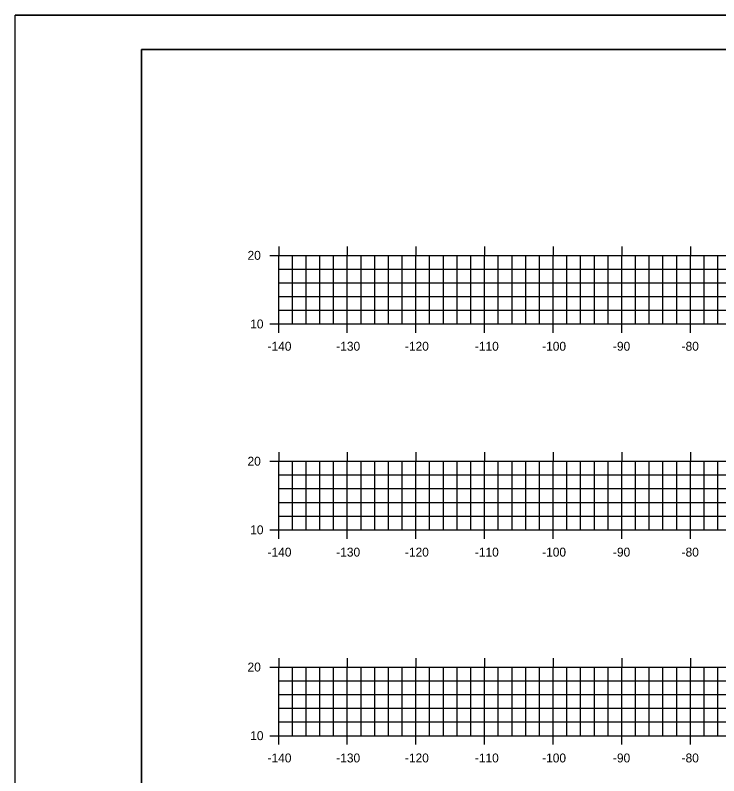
# Model space of a CAD drawing. Extents: x 40011 to 50684, y 49949 to 72236.
# Drawn here: x 41164.2 to 41266.7, y 69083.8 to 69194.6 of the extents above; entities that cross this region are included whole.
import ezdxf

# ---------------------------------------------------------------- set-up
doc = ezdxf.new("R2010")
doc.units = 0
for name, color, linetype in [('1', 7, 'Continuous'), ('41', 7, 'Continuous'), ('51', 7, 'Continuous'), ('53', 7, 'Continuous'), ('55', 7, 'Continuous'), ('60', 7, 'Continuous')]:
    doc.layers.add(name, color=color, linetype=linetype)

msp = doc.modelspace()

# ---------------------------------------------------------------- linework, layer by layer
at = {"layer": '1'}
for p, q in [((41513.59, 69194.6), (41164.2, 69194.6)), ((41182.59, 69189.6), (41182.59, 68979.6)), ((41512.59, 69189.6), (41182.59, 69189.6))]:
    msp.add_line(p, q, dxfattribs=at)
at = {"layer": '41'}
for points in [[(41164.2, 69194.6), (41513.59, 69194.6), (41513.59, 68974.6), (41164.2, 68974.6)], [(41182.59, 69189.6), (41512.59, 69189.6), (41512.59, 68979.6), (41182.59, 68979.6)]]:
    msp.add_lwpolyline(points, close=True, dxfattribs=at)
at = {"layer": '51'}
for p, q in [((41201.29, 69159.6), (41202.59, 69159.6)), ((41202.59, 69149.6), (41202.59, 69159.6)), ((41204.59, 69149.6), (41204.59, 69159.6)), ((41206.59, 69149.6), (41206.59, 69159.6)), ((41208.59, 69149.6), (41208.59, 69159.6)), ((41210.59, 69149.6), (41210.59, 69159.6)), ((41214.59, 69149.6), (41214.59, 69159.6)), ((41216.59, 69149.6), (41216.59, 69159.6)), ((41218.59, 69149.6), (41218.59, 69159.6)), ((41220.59, 69149.6), (41220.59, 69159.6)), ((41224.59, 69149.6), (41224.59, 69159.6)), ((41226.59, 69149.6), (41226.59, 69159.6)), ((41228.59, 69149.6), (41228.59, 69159.6)), ((41230.59, 69149.6), (41230.59, 69159.6)), ((41234.59, 69149.6), (41234.59, 69159.6)), ((41236.59, 69149.6), (41236.59, 69159.6)), ((41238.59, 69149.6), (41238.59, 69159.6)), ((41240.59, 69149.6), (41240.59, 69159.6)), ((41244.59, 69149.6), (41244.59, 69159.6)), ((41246.59, 69149.6), (41246.59, 69159.6)), ((41248.59, 69149.6), (41248.59, 69159.6)), ((41250.59, 69149.6), (41250.59, 69159.6)), ((41254.59, 69149.6), (41254.59, 69159.6)), ((41256.59, 69149.6), (41256.59, 69159.6)), ((41258.59, 69149.6), (41258.59, 69159.6)), ((41260.59, 69149.6), (41260.59, 69159.6)), ((41264.59, 69149.6), (41264.59, 69159.6)), ((41266.59, 69149.6), (41266.59, 69159.6)), ((41201.29, 69149.6), (41202.59, 69149.6)), ((41202.59, 69149.6), (41482.59, 69149.6)), ((41202.59, 69148.3), (41202.59, 69149.6)), ((41212.59, 69148.3), (41212.59, 69149.6)), ((41222.59, 69148.3), (41222.59, 69149.6)), ((41232.59, 69148.3), (41232.59, 69149.6)), ((41242.59, 69148.3), (41242.59, 69149.6)), ((41252.59, 69148.3), (41252.59, 69149.6)), ((41262.59, 69148.3), (41262.59, 69149.6)), ((41201.29, 69129.6), (41202.59, 69129.6)), ((41202.59, 69119.6), (41202.59, 69129.6)), ((41204.59, 69119.6), (41204.59, 69129.6)), ((41206.59, 69119.6), (41206.59, 69129.6)), ((41208.59, 69119.6), (41208.59, 69129.6)), ((41210.59, 69119.6), (41210.59, 69129.6)), ((41214.59, 69119.6), (41214.59, 69129.6)), ((41216.59, 69119.6), (41216.59, 69129.6)), ((41218.59, 69119.6), (41218.59, 69129.6)), ((41220.59, 69119.6), (41220.59, 69129.6)), ((41224.59, 69119.6), (41224.59, 69129.6)), ((41226.59, 69119.6), (41226.59, 69129.6)), ((41228.59, 69119.6), (41228.59, 69129.6)), ((41230.59, 69119.6), (41230.59, 69129.6)), ((41234.59, 69119.6), (41234.59, 69129.6)), ((41236.59, 69119.6), (41236.59, 69129.6)), ((41238.59, 69119.6), (41238.59, 69129.6)), ((41240.59, 69119.6), (41240.59, 69129.6)), ((41244.59, 69119.6), (41244.59, 69129.6)), ((41246.59, 69119.6), (41246.59, 69129.6)), ((41248.59, 69119.6), (41248.59, 69129.6)), ((41250.59, 69119.6), (41250.59, 69129.6)), ((41254.59, 69119.6), (41254.59, 69129.6)), ((41256.59, 69119.6), (41256.59, 69129.6)), ((41258.59, 69119.6), (41258.59, 69129.6)), ((41260.59, 69119.6), (41260.59, 69129.6)), ((41264.59, 69119.6), (41264.59, 69129.6)), ((41266.59, 69119.6), (41266.59, 69129.6)), ((41201.29, 69119.6), (41202.59, 69119.6)), ((41202.59, 69119.6), (41482.59, 69119.6)), ((41202.59, 69118.3), (41202.59, 69119.6)), ((41212.59, 69118.3), (41212.59, 69119.6)), ((41222.59, 69118.3), (41222.59, 69119.6)), ((41232.59, 69118.3), (41232.59, 69119.6)), ((41242.59, 69118.3), (41242.59, 69119.6)), ((41252.59, 69118.3), (41252.59, 69119.6)), ((41262.59, 69118.3), (41262.59, 69119.6)), ((41201.29, 69099.6), (41202.59, 69099.6)), ((41202.59, 69089.6), (41202.59, 69099.6)), ((41204.59, 69089.6), (41204.59, 69099.6)), ((41206.59, 69089.6), (41206.59, 69099.6)), ((41208.59, 69089.6), (41208.59, 69099.6)), ((41210.59, 69089.6), (41210.59, 69099.6)), ((41214.59, 69089.6), (41214.59, 69099.6)), ((41216.59, 69089.6), (41216.59, 69099.6)), ((41218.59, 69089.6), (41218.59, 69099.6)), ((41220.59, 69089.6), (41220.59, 69099.6)), ((41224.59, 69089.6), (41224.59, 69099.6)), ((41226.59, 69089.6), (41226.59, 69099.6)), ((41228.59, 69089.6), (41228.59, 69099.6)), ((41230.59, 69089.6), (41230.59, 69099.6)), ((41234.59, 69089.6), (41234.59, 69099.6)), ((41236.59, 69089.6), (41236.59, 69099.6)), ((41238.59, 69089.6), (41238.59, 69099.6)), ((41240.59, 69089.6), (41240.59, 69099.6)), ((41244.59, 69089.6), (41244.59, 69099.6)), ((41246.59, 69089.6), (41246.59, 69099.6)), ((41248.59, 69089.6), (41248.59, 69099.6)), ((41250.59, 69089.6), (41250.59, 69099.6)), ((41254.59, 69089.6), (41254.59, 69099.6)), ((41256.59, 69089.6), (41256.59, 69099.6)), ((41258.59, 69089.6), (41258.59, 69099.6)), ((41260.59, 69089.6), (41260.59, 69099.6)), ((41264.59, 69089.6), (41264.59, 69099.6)), ((41266.59, 69089.6), (41266.59, 69099.6)), ((41201.29, 69089.6), (41202.59, 69089.6)), ((41202.59, 69089.6), (41482.59, 69089.6)), ((41202.59, 69088.3), (41202.59, 69089.6)), ((41212.59, 69088.3), (41212.59, 69089.6)), ((41222.59, 69088.3), (41222.59, 69089.6)), ((41232.59, 69088.3), (41232.59, 69089.6)), ((41242.59, 69088.3), (41242.59, 69089.6)), ((41252.59, 69088.3), (41252.59, 69089.6)), ((41262.59, 69088.3), (41262.59, 69089.6))]:
    msp.add_line(p, q, dxfattribs=at)
at = {"layer": '53'}
for p, q in [((41202.59, 69157.6), (41482.59, 69157.6)), ((41202.59, 69155.6), (41482.59, 69155.6)), ((41202.59, 69153.6), (41482.59, 69153.6)), ((41202.59, 69151.6), (41482.59, 69151.6)), ((41202.59, 69127.6), (41482.59, 69127.6)), ((41202.59, 69125.6), (41482.59, 69125.6)), ((41202.59, 69123.6), (41482.59, 69123.6)), ((41202.59, 69121.6), (41482.59, 69121.6)), ((41202.59, 69097.6), (41482.59, 69097.6)), ((41202.59, 69095.6), (41482.59, 69095.6)), ((41202.59, 69093.6), (41482.59, 69093.6)), ((41202.59, 69091.6), (41482.59, 69091.6))]:
    msp.add_line(p, q, dxfattribs=at)
at = {"layer": '55'}
for p, q in [((41202.59, 69159.6), (41482.59, 69159.6)), ((41202.59, 69149.6), (41202.59, 69159.6)), ((41212.59, 69149.6), (41212.59, 69159.6)), ((41222.59, 69149.6), (41222.59, 69159.6)), ((41232.59, 69149.6), (41232.59, 69159.6)), ((41242.59, 69149.6), (41242.59, 69159.6)), ((41252.59, 69149.6), (41252.59, 69159.6)), ((41262.59, 69149.6), (41262.59, 69159.6)), ((41202.59, 69149.6), (41482.59, 69149.6)), ((41202.59, 69129.6), (41482.59, 69129.6)), ((41202.59, 69119.6), (41202.59, 69129.6)), ((41212.59, 69119.6), (41212.59, 69129.6)), ((41222.59, 69119.6), (41222.59, 69129.6)), ((41232.59, 69119.6), (41232.59, 69129.6)), ((41242.59, 69119.6), (41242.59, 69129.6)), ((41252.59, 69119.6), (41252.59, 69129.6)), ((41262.59, 69119.6), (41262.59, 69129.6)), ((41202.59, 69119.6), (41482.59, 69119.6)), ((41202.59, 69099.6), (41482.59, 69099.6)), ((41202.59, 69089.6), (41202.59, 69099.6)), ((41212.59, 69089.6), (41212.59, 69099.6)), ((41222.59, 69089.6), (41222.59, 69099.6)), ((41232.59, 69089.6), (41232.59, 69099.6)), ((41242.59, 69089.6), (41242.59, 69099.6)), ((41252.59, 69089.6), (41252.59, 69099.6)), ((41262.59, 69089.6), (41262.59, 69099.6)), ((41202.59, 69089.6), (41482.59, 69089.6))]:
    msp.add_line(p, q, dxfattribs=at)
at = {"layer": '60'}
for p, q in [((41202.59, 69160.9), (41202.59, 69159.6)), ((41212.59, 69160.9), (41212.59, 69159.6)), ((41222.59, 69160.9), (41222.59, 69159.6)), ((41232.59, 69160.9), (41232.59, 69159.6)), ((41242.59, 69160.9), (41242.59, 69159.6)), ((41252.59, 69160.9), (41252.59, 69159.6)), ((41262.59, 69160.9), (41262.59, 69159.6)), ((41202.59, 69130.9), (41202.59, 69129.6)), ((41212.59, 69130.9), (41212.59, 69129.6)), ((41222.59, 69130.9), (41222.59, 69129.6)), ((41232.59, 69130.9), (41232.59, 69129.6)), ((41242.59, 69130.9), (41242.59, 69129.6)), ((41252.59, 69130.9), (41252.59, 69129.6)), ((41262.59, 69130.9), (41262.59, 69129.6)), ((41202.59, 69100.9), (41202.59, 69099.6)), ((41212.59, 69100.9), (41212.59, 69099.6)), ((41222.59, 69100.9), (41222.59, 69099.6)), ((41232.59, 69100.9), (41232.59, 69099.6)), ((41242.59, 69100.9), (41242.59, 69099.6)), ((41252.59, 69100.9), (41252.59, 69099.6)), ((41262.59, 69100.9), (41262.59, 69099.6))]:
    msp.add_line(p, q, dxfattribs=at)

# ---------------------------------------------------------------- texts
at = {"layer": '51'}
for s, height, p in [('20', 1.3, (41198.05, 69158.95)), ('10', 1.3, (41198.44, 69148.95)), ('-', 0.0001, (41202.59, 69149.6)), ('-140', 1.3, (41200.97, 69145.7)), ('-130', 1.3, (41210.98, 69145.7)), ('-120', 1.3, (41220.99, 69145.7)), ('-110', 1.3, (41231.18, 69145.7)), ('-100', 1.3, (41240.98, 69145.7)), ('-90', 1.3, (41251.3, 69145.7)), ('-80', 1.3, (41261.3, 69145.7)), ('20', 1.3, (41198.05, 69128.95)), ('10', 1.3, (41198.44, 69118.95)), ('-', 0.0001, (41202.59, 69119.6)), ('-140', 1.3, (41200.97, 69115.7)), ('-130', 1.3, (41210.98, 69115.7)), ('-120', 1.3, (41220.99, 69115.7)), ('-110', 1.3, (41231.18, 69115.7)), ('-100', 1.3, (41240.98, 69115.7)), ('-90', 1.3, (41251.3, 69115.7)), ('-80', 1.3, (41261.3, 69115.7)), ('20', 1.3, (41198.05, 69098.95)), ('10', 1.3, (41198.44, 69088.95)), ('-', 0.0001, (41202.59, 69089.6)), ('-140', 1.3, (41200.97, 69085.7)), ('-130', 1.3, (41210.98, 69085.7)), ('-120', 1.3, (41220.99, 69085.7)), ('-110', 1.3, (41231.18, 69085.7)), ('-100', 1.3, (41240.98, 69085.7)), ('-90', 1.3, (41251.3, 69085.7)), ('-80', 1.3, (41261.3, 69085.7))]:
    msp.add_text(s, height=height, dxfattribs=at).set_placement(p)

doc.saveas('drawing.dxf')
